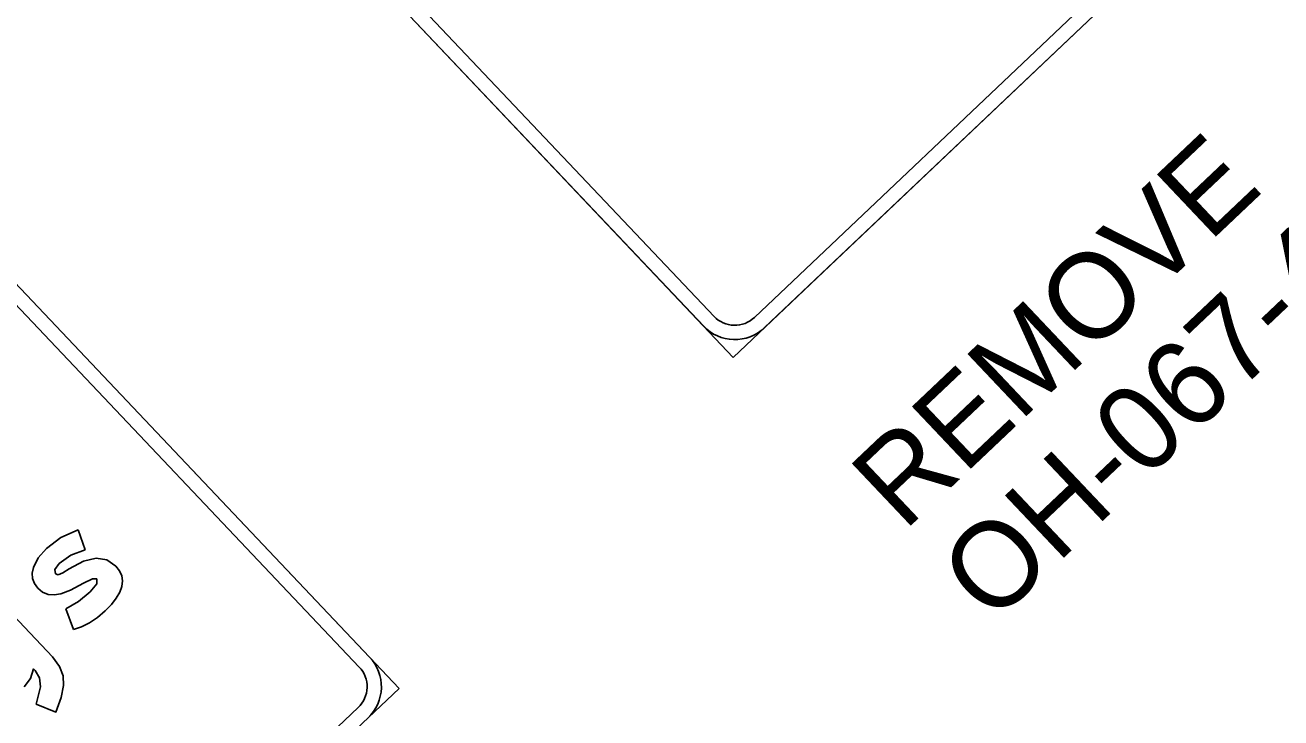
# Model space of a CAD drawing. Extents: x 1289840 to 1295361, y 220865 to 226414.
# Drawn here: x 1291512.4 to 1291600.3, y 222174.4 to 222222.9 of the extents above; entities that cross this region are included whole.
import ezdxf

# ---------------------------------------------------------------- set-up
doc = ezdxf.new("R2010")
doc.units = 0
doc.layers.add('P_TC_Signs_Permanent', color=7, linetype='Continuous')
doc.layers.add('R_OVHD_Sign', color=7, linetype='Continuous')

msp = doc.modelspace()

# ---------------------------------------------------------------- linework, layer by layer
at = {"layer": 'R_OVHD_Sign'}
for p, q in [((1291561.94, 222199.653), (1291614.198, 222249.181)), ((1291563.429, 222202.442), (1291611.333, 222247.843)), ((1291612.021, 222247.117), (1291564.117, 222201.716)), ((1291518.602, 222245.379), (1291561.94, 222199.653)), ((1291521.392, 222243.889), (1291560.602, 222202.518)), ((1291559.876, 222201.83), (1291520.666, 222243.201)), ((1291538.551, 222176.488), (1291497.277, 222220.036)), ((1291535.761, 222177.977), (1291498.615, 222217.171)), ((1291499.341, 222217.859), (1291536.487, 222178.665)), ((1291563.429, 222202.442), (1291563.429, 222202.442)), ((1291563.429, 222202.442), (1291563.429, 222202.442)), ((1291561.94, 222199.653), (1291561.94, 222199.653)), ((1291561.94, 222199.653), (1291561.94, 222199.653)), ((1291516.09, 222187.58), (1291514.88, 222187.046)), ((1291516.577, 222186.181), (1291516.09, 222187.58)), ((1291514.88, 222187.046), (1291513.861, 222186.286)), ((1291513.293, 222185.628), (1291512.951, 222184.957)), ((1291513.861, 222186.286), (1291513.293, 222185.628)), ((1291514.762, 222185.232), (1291515.578, 222185.81)), ((1291515.578, 222185.81), (1291516.577, 222186.181)), ((1291517.343, 222185.598), (1291516.458, 222185.389)), ((1291518.098, 222185.482), (1291517.343, 222185.598)), ((1291518.729, 222185.047), (1291518.098, 222185.482)), ((1291512.951, 222184.957), (1291512.871, 222184.546)), ((1291514.437, 222184.805), (1291514.762, 222185.232)), ((1291514.488, 222184.496), (1291514.437, 222184.805)), ((1291515.449, 222184.863), (1291515.019, 222184.578)), ((1291516.458, 222185.389), (1291515.449, 222184.863)), ((1291518.982, 222184.717), (1291518.729, 222185.047)), ((1291519.133, 222184.371), (1291518.982, 222184.717)), ((1291512.871, 222184.546), (1291512.895, 222184.168)), ((1291512.895, 222184.168), (1291513.025, 222183.821)), ((1291513.025, 222183.821), (1291513.256, 222183.507)), ((1291514.691, 222184.444), (1291514.488, 222184.496)), ((1291515.019, 222184.578), (1291514.691, 222184.444)), ((1291515.534, 222183.351), (1291516.448, 222183.843)), ((1291516.448, 222183.843), (1291517.077, 222184.154)), ((1291517.386, 222183.805), (1291516.922, 222183.252)), ((1291517.077, 222184.154), (1291517.388, 222184.152)), ((1291517.388, 222184.152), (1291517.386, 222183.805)), ((1291519.185, 222184.006), (1291519.133, 222184.371)), ((1291519.139, 222183.625), (1291519.185, 222184.006)), ((1291513.256, 222183.507), (1291513.596, 222183.23)), ((1291513.596, 222183.23), (1291513.979, 222183.069)), ((1291513.979, 222183.069), (1291514.406, 222183.023)), ((1291514.406, 222183.023), (1291514.878, 222183.096)), ((1291514.878, 222183.096), (1291515.534, 222183.351)), ((1291516.922, 222183.252), (1291516.096, 222182.569)), ((1291518.749, 222182.803), (1291518.994, 222183.222)), ((1291518.994, 222183.222), (1291519.139, 222183.625)), ((1291516.096, 222182.569), (1291515.23, 222182.046)), ((1291515.23, 222182.046), (1291515.75, 222180.601)), ((1291517.964, 222181.909), (1291518.406, 222182.365)), ((1291518.406, 222182.365), (1291518.749, 222182.803)), ((1291516.326, 222180.799), (1291516.887, 222181.084)), ((1291516.887, 222181.084), (1291517.433, 222181.452)), ((1291517.433, 222181.452), (1291517.964, 222181.909)), ((1291515.75, 222180.601), (1291516.326, 222180.799)), ((1291535.761, 222177.977), (1291535.761, 222177.977)), ((1291535.761, 222177.977), (1291535.761, 222177.977)), ((1291460.163, 222102.195), (1291538.551, 222176.488)), ((1291461.653, 222104.985), (1291535.685, 222175.15))]:
    msp.add_line(p, q, dxfattribs=at)
for points in [[(1291513.131, 222175.376), (1291514.525, 222174.835), (1291514.888, 222175.842), (1291515.048, 222176.701), (1291515.035, 222177.368), (1291514.785, 222178.026), (1291514.281, 222178.692), (1291510.338, 222182.852)], [(1291512.307, 222176.585), (1291512.753, 222177.17), (1291512.958, 222177.855), (1291513.075, 222177.741), (1291513.385, 222177.222), (1291513.447, 222176.588), (1291513.131, 222175.376)]]:
    msp.add_lwpolyline(points, dxfattribs=at)
for centre, radius, start, end in [((1291562.053, 222203.894), 2, 223.46346, 313.46367), ((1291562.053, 222203.894), 3, 223.46346, 313.46367), ((1291534.31, 222176.602), 3, 313.46367, 43.46388), ((1291534.31, 222176.602), 2, 313.46367, 43.46388)]:
    msp.add_arc(centre, radius, start, end, dxfattribs=at)

# ---------------------------------------------------------------- texts
at = {"layer": 'P_TC_Signs_Permanent'}
for s, p in [('OH-067-43-STA49+90NB-D', (1291580.082, 222180.884)), ('REMOVE', (1291573.894, 222187.419))]:
    msp.add_text(s, height=6, rotation=43.43866, dxfattribs=at).set_placement(p)

doc.saveas('drawing.dxf')
